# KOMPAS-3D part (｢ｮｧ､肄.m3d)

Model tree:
1. Эскиз:2
2. Операция выдавливания:1
     Расстояние 1 = 35; Угол 1 = 4
3. Эскиз:3
4. Вырезать элемент выдавливания:1
     Расстояние 2 = 35; Угол 2 = 1.91; Расстояние 1 = 10
5. Оболочка:2
     Толщина стенки 2 = 1
6. Эскиз:8
7. Вырезать элемент выдавливания:4
     Расстояние 2 = 11.1672; Расстояние 1 = 11.1672
8. Эскиз:10
9. Операция выдавливания:4
     Расстояние 1 = 1; Угол 2 = 1.98
10. Эскиз:16
11. Операция выдавливания:9
     Расстояние 1 = 2; Расстояние 2 = 1; Угол 2 = 4
12. Эскиз:17
13. Операция выдавливания:10
     Расстояние 1 = 15; Расстояние 2 = 15; Угол 2 = 4
14. Эскиз:18
15. Операция выдавливания:11
     Расстояние 1 = 1; Расстояние 2 = 15; Угол 2 = 4
16. Скругление:1
     Радиус = 1
17. Скругление:2
     Радиус = 1
18. Скругление:3
     Радиус = 1
19. Эскиз:19
20. Вырезать элемент выдавливания:5
     Расстояние 1 = 15.9339
21. Эскиз:20
22. Вырезать элемент выдавливания:6
     Расстояние 1 = 17
23. Эскиз:21
24. Вырезать элемент выдавливания:7
     Расстояние 2 = 27; Расстояние 1 = 15
25. Эскиз:22
26. Вырезать элемент выдавливания:8
     Расстояние 1 = 15
